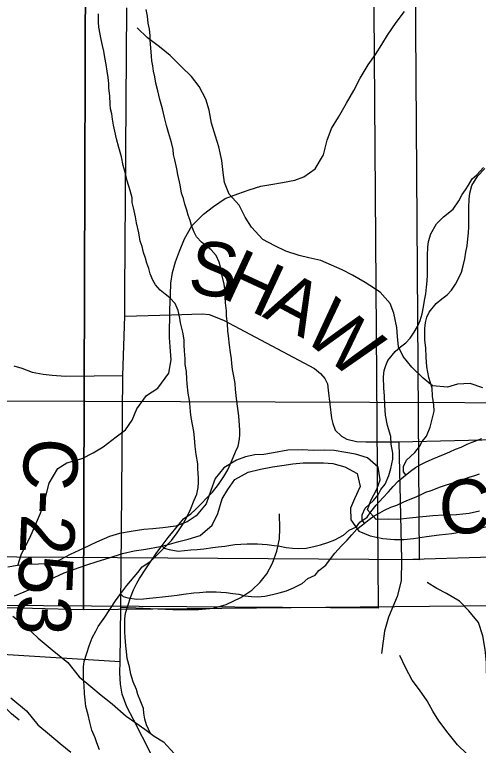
# Model space of a CAD drawing. Extents: x -21.1 to 50.3, y 0 to 22.1.
# Drawn here: x 7.45 to 7.937, y 14.756 to 15.523 of the extents above; entities that cross this region are included whole.
import ezdxf

# ---------------------------------------------------------------- set-up
doc = ezdxf.new("R2010")
doc.units = 0
for name, color, linetype in [('GM_X_County_Road', 7, 'Continuous'), ('GM_X_County_Road_Text', 7, 'Continuous'), ('GM_X_Major_River', 7, 'Continuous'), ('GM_X_Minor_River', 7, 'Continuous'), ('GM_X_Section', 7, 'Continuous'), ('GM_X_Township_Road', 7, 'Continuous')]:
    doc.layers.add(name, color=color, linetype=linetype)

msp = doc.modelspace()

# ---------------------------------------------------------------- linework, layer by layer
at = {"layer": 'GM_X_County_Road'}
for points in [[(7.6645, 14.30049), (7.66528, 14.41199), (7.66666, 14.54699), (7.66735, 14.60343), (7.66021, 14.61749), (7.62842, 14.67761), (7.57474, 14.78243), (7.56737, 14.79649), (7.56276, 14.80962), (7.56092, 14.82021), (7.56023, 14.83219), (7.56046, 14.84394), (7.56138, 14.90107), (7.56345, 15.14435), (7.56542, 15.20657), (7.56542, 15.2311), (7.5677, 15.5301)], [(7.56542, 15.20657), (7.61447, 15.20776), (7.64678, 15.20896), (7.65399, 15.20816), (7.66892, 15.20238), (7.76465, 15.15152), (7.77102, 15.14619), (7.7754, 15.14112), (7.77816, 15.13559), (7.77901, 15.12879), (7.78231, 15.09943), (7.78369, 15.0939), (7.78619, 15.0869), (7.7929, 15.08053), (7.79866, 15.07754), (7.8088, 15.07501), (7.81848, 15.07454), (7.85301, 15.07456), (7.9701, 15.07751)]]:
    msp.add_lwpolyline(points, dxfattribs=at)
at = {"layer": 'GM_X_Major_River'}
for points in [[(7.8519, 14.99319), (7.84202, 14.99334), (7.82911, 14.99316), (7.82015, 15.00317), (7.82372, 15.01299), (7.82998, 15.02505), (7.83355, 15.03487), (7.83148, 15.04782), (7.82024, 15.05787), (7.80776, 15.06148), (7.79754, 15.06353), (7.78503, 15.06562), (7.77516, 15.06577), (7.76338, 15.06557), (7.752, 15.06612), (7.73642, 15.06598), (7.72157, 15.06317), (7.71129, 15.06143), (7.70178, 15.06081), (7.69225, 15.05867), (7.68271, 15.0554), (7.66929, 15.04725), (7.66038, 15.03599), (7.65563, 15.02352), (7.65085, 15.00954), (7.6404, 14.99678), (7.6308, 14.99047), (7.61896, 14.98609), (7.60526, 14.9844), (7.59499, 14.98342), (7.58548, 14.98242), (7.57216, 14.98034), (7.55997, 14.97825), (7.54929, 14.97537), (7.53552, 14.96912), (7.52174, 14.9625), (7.50797, 14.95625), (7.49763, 14.95071), (7.48808, 14.94705), (7.47477, 14.94611), (7.463, 14.94591), (7.45273, 14.94493), (7.44244, 14.94319)], [(7.44957, 14.91307), (7.45989, 14.91709), (7.47022, 14.92187), (7.48093, 14.92703), (7.49127, 14.93219), (7.5016, 14.93697), (7.51153, 14.94062), (7.52566, 14.94534), (7.53635, 14.94898), (7.54894, 14.95297), (7.56306, 14.95731), (7.57526, 14.96016), (7.58744, 14.96188), (7.60268, 14.96469), (7.61221, 14.9672), (7.62213, 14.97009), (7.63205, 14.9726), (7.64464, 14.9762), (7.65696, 14.98703), (7.66323, 14.99947), (7.66764, 15.0146), (7.67349, 15.02439), (7.68087, 15.03491), (7.69504, 15.04268), (7.70801, 15.0459), (7.72058, 15.04837), (7.73009, 15.04974), (7.7419, 15.05146), (7.75255, 15.05244), (7.76356, 15.05265), (7.77382, 15.0525), (7.78368, 15.05197), (7.79654, 15.04835), (7.80934, 15.04132), (7.81255, 15.0276)], [(7.81255, 15.0276), (7.80665, 15.01477), (7.80232, 15.00496), (7.80252, 14.9928), (7.81107, 14.98089), (7.82314, 14.97577), (7.8364, 14.97329), (7.84853, 14.97197), (7.85841, 14.9722), (7.8683, 14.97319), (7.882, 14.97526), (7.89532, 14.97696), (7.90864, 14.97827), (7.92082, 14.98037), (7.93416, 14.98282), (7.94827, 14.98641)], [(7.93787, 15.00176), (7.92681, 14.99927), (7.9135, 14.99795), (7.9002, 14.99777), (7.8888, 14.99681), (7.87472, 14.9955), (7.86445, 14.99452), (7.8519, 14.99319)], [(7.44786, 14.89171), (7.46123, 14.88119), (7.47461, 14.8684), (7.48913, 14.85637), (7.50555, 14.84284), (7.51743, 14.82813), (7.52965, 14.81798), (7.54073, 14.80859), (7.55219, 14.79957), (7.56671, 14.78678), (7.57701, 14.77965), (7.58655, 14.7729), (7.59609, 14.76577)], [(7.44584, 14.80585), (7.46226, 14.79232), (7.47414, 14.77762), (7.48637, 14.76747), (7.49744, 14.75807), (7.5089, 14.74905)], [(7.59609, 14.76577), (7.60601, 14.75977), (7.61749, 14.74734), (7.62251, 14.73676), (7.62828, 14.72655), (7.63408, 14.71332), (7.64064, 14.69895), (7.64529, 14.68723), (7.65111, 14.67095), (7.65384, 14.66111), (7.66001, 14.6494), (7.67149, 14.63621), (7.68104, 14.62907), (7.69323, 14.62272), (7.71, 14.61298), (7.71952, 14.60927), (7.73096, 14.60215), (7.74315, 14.59541), (7.75687, 14.58869), (7.77638, 14.581)]]:
    msp.add_lwpolyline(points, dxfattribs=at)
at = {"layer": 'GM_X_Minor_River'}
for points in [[(7.45314, 14.94497), (7.45709, 14.95702), (7.46571, 14.97398), (7.47162, 14.98757), (7.47674, 14.99965), (7.48232, 15.01628), (7.48596, 15.03104), (7.49494, 15.04648), (7.50453, 15.05241), (7.52055, 15.0571), (7.53204, 15.06301), (7.54277, 15.0693), (7.55623, 15.07973), (7.56622, 15.08718), (7.57321, 15.09733), (7.57795, 15.10904), (7.58805, 15.12332), (7.59994, 15.13073), (7.61157, 15.14651), (7.61407, 15.16053), (7.61314, 15.17422), (7.61216, 15.18411), (7.61261, 15.21298), (7.61323, 15.22892), (7.6138, 15.24107), (7.6155, 15.25244), (7.6187, 15.26341), (7.62268, 15.27474), (7.6282, 15.28758), (7.63562, 15.30114), (7.64797, 15.31349), (7.65835, 15.32169), (7.67063, 15.32986), (7.684, 15.33497), (7.69584, 15.33897), (7.70806, 15.34297), (7.71872, 15.3447), (7.7309, 15.3468), (7.74386, 15.34926), (7.7534, 15.35253), (7.76531, 15.36109), (7.77389, 15.37577), (7.77793, 15.39129), (7.7823, 15.40338), (7.7897, 15.41542), (7.79828, 15.43011), (7.8057, 15.44329), (7.81236, 15.4561), (7.82093, 15.47003), (7.8287, 15.48093), (7.83532, 15.49146), (7.84117, 15.50125), (7.85011, 15.51479), (7.85902, 15.52605)], [(7.54798, 15.45705), (7.5468, 15.4635), (7.546, 15.47072), (7.54444, 15.47792), (7.54326, 15.48437), (7.54209, 15.49045), (7.54053, 15.4969), (7.53817, 15.5098), (7.53776, 15.51512), (7.53771, 15.52385)], [(7.59127, 15.50756), (7.59009, 15.51402), (7.58929, 15.52123), (7.58773, 15.52844)], [(7.59243, 14.7685), (7.58812, 14.77743), (7.58657, 14.7835), (7.58539, 14.78995), (7.58498, 14.79488), (7.58228, 14.80171), (7.57919, 14.80929), (7.57764, 14.8146), (7.57417, 14.82255), (7.57184, 14.8309), (7.57027, 14.83849), (7.56794, 14.84721), (7.56714, 14.85442), (7.56634, 14.8605), (7.56591, 14.86961), (7.5655, 14.87531), (7.56542, 14.88898), (7.56615, 14.89469), (7.56877, 14.90344), (7.57139, 14.91105), (7.57439, 14.91942), (7.57816, 14.92628), (7.58079, 14.93124), (7.58759, 14.94115), (7.59891, 14.9583), (7.60458, 14.96593), (7.611, 14.97433), (7.62234, 14.98806), (7.62688, 14.99379), (7.63484, 14.99915), (7.63976, 15.00374), (7.65755, 15.02169), (7.6636, 15.0297), (7.66926, 15.03809), (7.67341, 15.04533), (7.67755, 15.05409), (7.68168, 15.06398), (7.68431, 15.07008), (7.68579, 15.0773), (7.68614, 15.08224), (7.68612, 15.08718), (7.6853, 15.09667), (7.68527, 15.10199), (7.68369, 15.11186), (7.68251, 15.12021), (7.68169, 15.12933), (7.68128, 15.13578), (7.67971, 15.14337), (7.67853, 15.15058), (7.67773, 15.15665), (7.67733, 15.16159), (7.67653, 15.16842), (7.67534, 15.17602), (7.67415, 15.18588), (7.67374, 15.19082), (7.67331, 15.1988), (7.67213, 15.20639), (7.6721, 15.21209), (7.67129, 15.22044), (7.67087, 15.22652), (7.67084, 15.23221), (7.66965, 15.24018), (7.66732, 15.25005), (7.66653, 15.25498), (7.66458, 15.26295), (7.66149, 15.27015), (7.65613, 15.2762), (7.65116, 15.27997), (7.64581, 15.28412), (7.64083, 15.28979), (7.63814, 15.29471), (7.63543, 15.30153), (7.63388, 15.30684), (7.63195, 15.31253), (7.6304, 15.31784), (7.62846, 15.32391), (7.6269, 15.32998), (7.62497, 15.33567), (7.62339, 15.3444), (7.62105, 15.35502), (7.61988, 15.36109), (7.61792, 15.37058), (7.61636, 15.37627), (7.61634, 15.3812), (7.61439, 15.38879), (7.61129, 15.39903), (7.60934, 15.40662), (7.60701, 15.41496), (7.60506, 15.42407), (7.60234, 15.43393), (7.60001, 15.44303), (7.59806, 15.451), (7.59688, 15.45745), (7.5957, 15.46352), (7.59491, 15.46922), (7.59374, 15.47453), (7.59333, 15.47947), (7.5929, 15.4882), (7.59209, 15.49617), (7.59207, 15.50111), (7.59127, 15.50756)], [(7.94127, 15.13112), (7.92794, 15.13594), (7.91467, 15.13505), (7.90407, 15.13192), (7.8885, 15.13329), (7.87856, 15.14155), (7.86669, 15.15284), (7.85748, 15.16415), (7.85284, 15.17437), (7.8516, 15.18499), (7.85114, 15.19449), (7.84797, 15.20966), (7.84408, 15.21988), (7.83335, 15.23156), (7.8177, 15.24167), (7.80435, 15.24952), (7.79367, 15.25512), (7.78225, 15.25995), (7.7712, 15.26479), (7.75865, 15.26771), (7.74838, 15.27027), (7.7343, 15.2747), (7.72286, 15.28029), (7.71028, 15.28701), (7.6984, 15.29982), (7.69185, 15.31039), (7.68529, 15.32287), (7.67494, 15.33455), (7.6699, 15.34666), (7.66866, 15.35729), (7.66741, 15.36982), (7.66425, 15.38422), (7.66073, 15.39521), (7.65643, 15.40885), (7.65403, 15.4225), (7.65051, 15.43425), (7.64357, 15.44748), (7.6355, 15.45804), (7.62478, 15.4682), (7.61291, 15.47986), (7.60182, 15.48926), (7.58922, 15.49864), (7.5785, 15.50917)], [(7.53899, 14.75119), (7.5359, 14.75877), (7.53435, 14.76408), (7.53088, 14.77204), (7.52855, 14.78038), (7.52699, 14.78797), (7.52465, 14.7967), (7.52385, 14.80391), (7.52306, 14.80998), (7.52262, 14.8191), (7.52221, 14.82479), (7.52213, 14.83847), (7.52286, 14.84417), (7.52548, 14.85292), (7.5281, 14.86054), (7.5311, 14.86891), (7.53487, 14.87577), (7.5375, 14.88072), (7.5443, 14.89063), (7.55562, 14.90779), (7.56129, 14.91542), (7.56771, 14.92381), (7.57906, 14.93755), (7.58359, 14.94327), (7.59155, 14.94863), (7.59648, 14.95322), (7.61427, 14.97117), (7.62031, 14.97918), (7.62597, 14.98757), (7.63012, 14.99481), (7.63426, 15.00357), (7.63839, 15.01347), (7.64102, 15.01956), (7.6425, 15.02679), (7.64285, 15.03173), (7.64283, 15.03667), (7.64201, 15.04616), (7.64198, 15.05148), (7.64041, 15.06135), (7.63922, 15.0697), (7.6384, 15.07881), (7.63799, 15.08526), (7.63642, 15.09285), (7.63524, 15.10006), (7.63445, 15.10614), (7.63404, 15.11107), (7.63324, 15.11791), (7.63205, 15.1255), (7.63086, 15.13537), (7.63045, 15.14031), (7.63002, 15.14828), (7.62884, 15.15587), (7.62881, 15.16157), (7.628, 15.16992), (7.62758, 15.176), (7.62755, 15.18169), (7.62637, 15.18967), (7.62403, 15.19953), (7.62324, 15.20447), (7.62129, 15.21243), (7.6182, 15.21963), (7.61284, 15.22568), (7.60787, 15.22945), (7.60252, 15.2336), (7.59754, 15.23927), (7.59485, 15.2442), (7.59215, 15.25102), (7.5906, 15.25633), (7.58866, 15.26202), (7.58711, 15.26732), (7.58517, 15.27339), (7.58361, 15.27946), (7.58168, 15.28515), (7.5801, 15.29388), (7.57776, 15.3045), (7.57659, 15.31057), (7.57463, 15.32006), (7.57308, 15.32575), (7.57305, 15.33069), (7.5711, 15.33828), (7.568, 15.34851), (7.56606, 15.3561), (7.56372, 15.36445), (7.56177, 15.37355), (7.55905, 15.38342), (7.55672, 15.39252), (7.55477, 15.40049), (7.55359, 15.40694), (7.55241, 15.41301), (7.55162, 15.4187), (7.55045, 15.42401), (7.55004, 15.42895), (7.54961, 15.43768), (7.54881, 15.44566), (7.54878, 15.4506), (7.54798, 15.45705)], [(7.81716, 14.98937), (7.81474, 14.99241), (7.81471, 14.99811), (7.81772, 15.00496), (7.82643, 15.01299), (7.83134, 15.01909), (7.83435, 15.02443), (7.83889, 15.03015), (7.84265, 15.03929), (7.84451, 15.04652), (7.84674, 15.0564), (7.8467, 15.06286), (7.84513, 15.07197), (7.8447, 15.08033), (7.84121, 15.0917), (7.83925, 15.10271), (7.83843, 15.11296), (7.83799, 15.12283), (7.83719, 15.13081), (7.83712, 15.14296), (7.83784, 15.14943), (7.83934, 15.15475), (7.84159, 15.16008), (7.84915, 15.16924), (7.85483, 15.17421), (7.86052, 15.17842), (7.86506, 15.18339), (7.86921, 15.18949), (7.8726, 15.19558), (7.87561, 15.20206), (7.87748, 15.20891), (7.87896, 15.21613), (7.88006, 15.22297), (7.88155, 15.22982), (7.88227, 15.23704), (7.88299, 15.2435), (7.88334, 15.24958), (7.88323, 15.26972), (7.88356, 15.27884), (7.88428, 15.28492), (7.88652, 15.29291), (7.89256, 15.3032), (7.90013, 15.31084), (7.90998, 15.31887), (7.91602, 15.32764), (7.91941, 15.33412), (7.92319, 15.33907), (7.9262, 15.34403), (7.92998, 15.35051), (7.9349, 15.35472), (7.94209, 15.36235)], [(7.86045, 15.03989), (7.85803, 15.04293), (7.858, 15.04863), (7.86101, 15.05548), (7.86972, 15.0635), (7.87463, 15.06961), (7.87764, 15.07494), (7.88218, 15.08067), (7.88593, 15.0898), (7.8878, 15.09703), (7.89003, 15.10692), (7.88999, 15.11338), (7.88842, 15.12249), (7.88799, 15.13084), (7.8845, 15.14222), (7.88254, 15.15323), (7.88172, 15.16348), (7.88128, 15.17335), (7.88047, 15.18132), (7.88041, 15.19348), (7.88113, 15.19994), (7.88262, 15.20527), (7.88488, 15.2106), (7.89244, 15.21976), (7.89812, 15.22473), (7.90381, 15.22894), (7.90835, 15.2339), (7.9125, 15.24), (7.91589, 15.2461), (7.9189, 15.25257), (7.92076, 15.25942), (7.92225, 15.26665), (7.92335, 15.27349), (7.92484, 15.28034), (7.92556, 15.28756), (7.92628, 15.29402), (7.92663, 15.3001), (7.92652, 15.32023), (7.92685, 15.32935), (7.92757, 15.33543), (7.92981, 15.34342), (7.93585, 15.35371), (7.94342, 15.36135)], [(7.60427, 14.96552), (7.60688, 14.96291), (7.61183, 14.96142), (7.62136, 14.95995), (7.62821, 14.96037), (7.63468, 14.96116), (7.64152, 14.96158), (7.64837, 14.96238), (7.65788, 14.96357), (7.66358, 14.96436), (7.67043, 14.96516), (7.68108, 14.96673), (7.68717, 14.96715), (7.69402, 14.96757), (7.70468, 14.96763), (7.70962, 14.96727), (7.71496, 14.96692), (7.72219, 14.96582), (7.72829, 14.96509), (7.73477, 14.96361), (7.74162, 14.96289), (7.7481, 14.96255), (7.75571, 14.96297), (7.76369, 14.96491), (7.77091, 14.96647), (7.77851, 14.96879), (7.78573, 14.97187), (7.79484, 14.97648), (7.8009, 14.98183), (7.80849, 14.98529), (7.81227, 14.99025), (7.81985, 14.99561), (7.82363, 15.00095), (7.8293, 15.0082), (7.83611, 15.01583), (7.84216, 15.02195), (7.84708, 15.02767), (7.85237, 15.0334), (7.85806, 15.03799), (7.86526, 15.04373), (7.87057, 15.04755), (7.87626, 15.05063), (7.88119, 15.05331), (7.88803, 15.05639), (7.8941, 15.0587), (7.9017, 15.06216), (7.90663, 15.06409), (7.91271, 15.06678), (7.9184, 15.06909), (7.92486, 15.07216), (7.93018, 15.07409), (7.94005, 15.07795)], [(7.56098, 14.915), (7.56359, 14.91239), (7.56855, 14.9109), (7.57807, 14.90943), (7.58492, 14.90985), (7.59139, 14.91065), (7.59824, 14.91106), (7.60508, 14.91186), (7.61459, 14.91305), (7.6203, 14.91384), (7.62714, 14.91464), (7.63779, 14.91622), (7.64388, 14.91663), (7.65073, 14.91705), (7.66139, 14.91711), (7.66634, 14.91676), (7.67167, 14.91641), (7.67891, 14.91531), (7.685, 14.91458), (7.69148, 14.9131), (7.69833, 14.91237), (7.70481, 14.91203), (7.71242, 14.91245), (7.7204, 14.9144), (7.72762, 14.91595), (7.73522, 14.91827), (7.74244, 14.92136), (7.75155, 14.92596), (7.75761, 14.93131), (7.7652, 14.93477), (7.76898, 14.93973), (7.77656, 14.94509), (7.78034, 14.95043), (7.78601, 14.95768), (7.79282, 14.96532), (7.79887, 14.97143), (7.80379, 14.97715), (7.80909, 14.98288), (7.81477, 14.98747), (7.82197, 14.99321), (7.82728, 14.99704), (7.83297, 15.00011), (7.8379, 15.00279), (7.84474, 15.00587), (7.85081, 15.00818), (7.85841, 15.01165), (7.86335, 15.01357), (7.86942, 15.01626), (7.87512, 15.01857), (7.88157, 15.02165), (7.88689, 15.02358), (7.89676, 15.02743), (7.90208, 15.02898), (7.91424, 15.03285), (7.92032, 15.03516), (7.92678, 15.03747), (7.93286, 15.03941), (7.9378, 15.04095)], [(7.94777, 14.74515), (7.94841, 14.75808), (7.94793, 14.76985), (7.94783, 14.78049), (7.94735, 14.79226), (7.94685, 14.80556), (7.94673, 14.81847), (7.94508, 14.83328), (7.945, 14.84278), (7.94373, 14.85682), (7.94133, 14.87086), (7.93665, 14.88487), (7.92667, 14.89732), (7.91671, 14.90748), (7.90298, 14.91533), (7.89307, 14.92056), (7.88276, 14.92692)], [(7.9244, 14.74722), (7.91459, 14.75676), (7.90481, 14.76897), (7.89503, 14.78192), (7.88864, 14.79183), (7.88265, 14.80287), (7.87475, 14.8143), (7.86723, 14.82459), (7.86011, 14.83791), (7.85412, 14.85047)]]:
    msp.add_lwpolyline(points, dxfattribs=at)
at = {"layer": 'GM_X_Section'}
for points in [[(7.42125, 16.12212), (8.40937, 16.11144), (8.41946, 15.11372), (7.42449, 15.11725)], [(6.85861, 15.97246), (7.36725, 15.97553), (7.86729, 15.96487), (7.87451, 14.95066), (6.87078, 14.95753)], [(7.52522, 15.9214), (7.52217, 14.89823), (6.98631, 14.91225), (6.49861, 14.89749), (6.50469, 15.92066), (6.55964, 15.91994)], [(6.81532, 15.92194), (7.32396, 15.92501), (7.824, 15.91436), (7.83122, 14.90014), (6.82749, 14.90702)], [(7.52522, 15.9214), (7.57297, 15.92106), (8.53439, 15.91417), (8.53889, 14.90805), (7.52217, 14.89823)]]:
    msp.add_lwpolyline(points, close=True, dxfattribs=at)
at = {"layer": 'GM_X_Township_Road'}
for points in [[(7.44894, 15.15444), (7.45725, 15.15172), (7.46808, 15.1478), (7.4796, 15.1455), (7.48927, 15.14458), (7.5031, 15.14366), (7.56345, 15.14435)], [(7.85301, 15.07456), (7.8558, 14.95059), (7.85556, 14.92866), (7.85127, 14.91236), (7.84226, 14.89048), (7.83797, 14.87589), (7.83497, 14.8523)], [(7.56138, 14.90107), (7.61579, 14.8985), (7.64293, 14.89849), (7.6586, 14.90015), (7.67196, 14.90384), (7.68716, 14.91121), (7.69868, 14.91904), (7.70767, 14.92734), (7.71435, 14.93609), (7.72034, 14.94715), (7.72516, 14.95971), (7.7278, 14.97282), (7.72817, 14.98355), (7.72771, 14.99898)], [(7.99792, 14.84814), (7.99798, 14.85101), (7.99841, 14.8849), (7.99818, 14.91376), (7.99652, 14.92181), (7.99462, 14.92868), (7.98894, 14.93697), (7.98373, 14.94241), (7.97663, 14.94715), (7.97047, 14.94999), (7.96218, 14.95236), (7.95058, 14.95354), (7.8558, 14.95059)], [(7.42546, 14.85247), (7.56046, 14.84394)], [(7.45449, 14.78266), (7.44643, 14.78911), (7.43767, 14.79787), (7.42961, 14.81008), (7.42638, 14.82137), (7.42546, 14.83127), (7.42546, 14.85247)]]:
    msp.add_lwpolyline(points, dxfattribs=at)

# ---------------------------------------------------------------- texts
at = {"layer": 'GM_X_County_Road_Text'}
for s, height, rotation, p in [('S', 0.05682, 351.80472, (7.63021, 15.23125)), ('H', 0.05682, 335.13429, (7.66398, 15.22702)), ('A', 0.05682, 332.04194, (7.70862, 15.20636)), ('W', 0.05682, 320.01271, (7.75018, 15.18468)), ('C-253', 0.056818, 267.52165, (7.4604, 15.07968)), ('C-199', 0.056818, 0.26945, (7.89501, 14.97836))]:
    msp.add_text(s, height=height, rotation=rotation, dxfattribs=at).set_placement(p)

doc.saveas('drawing.dxf')
